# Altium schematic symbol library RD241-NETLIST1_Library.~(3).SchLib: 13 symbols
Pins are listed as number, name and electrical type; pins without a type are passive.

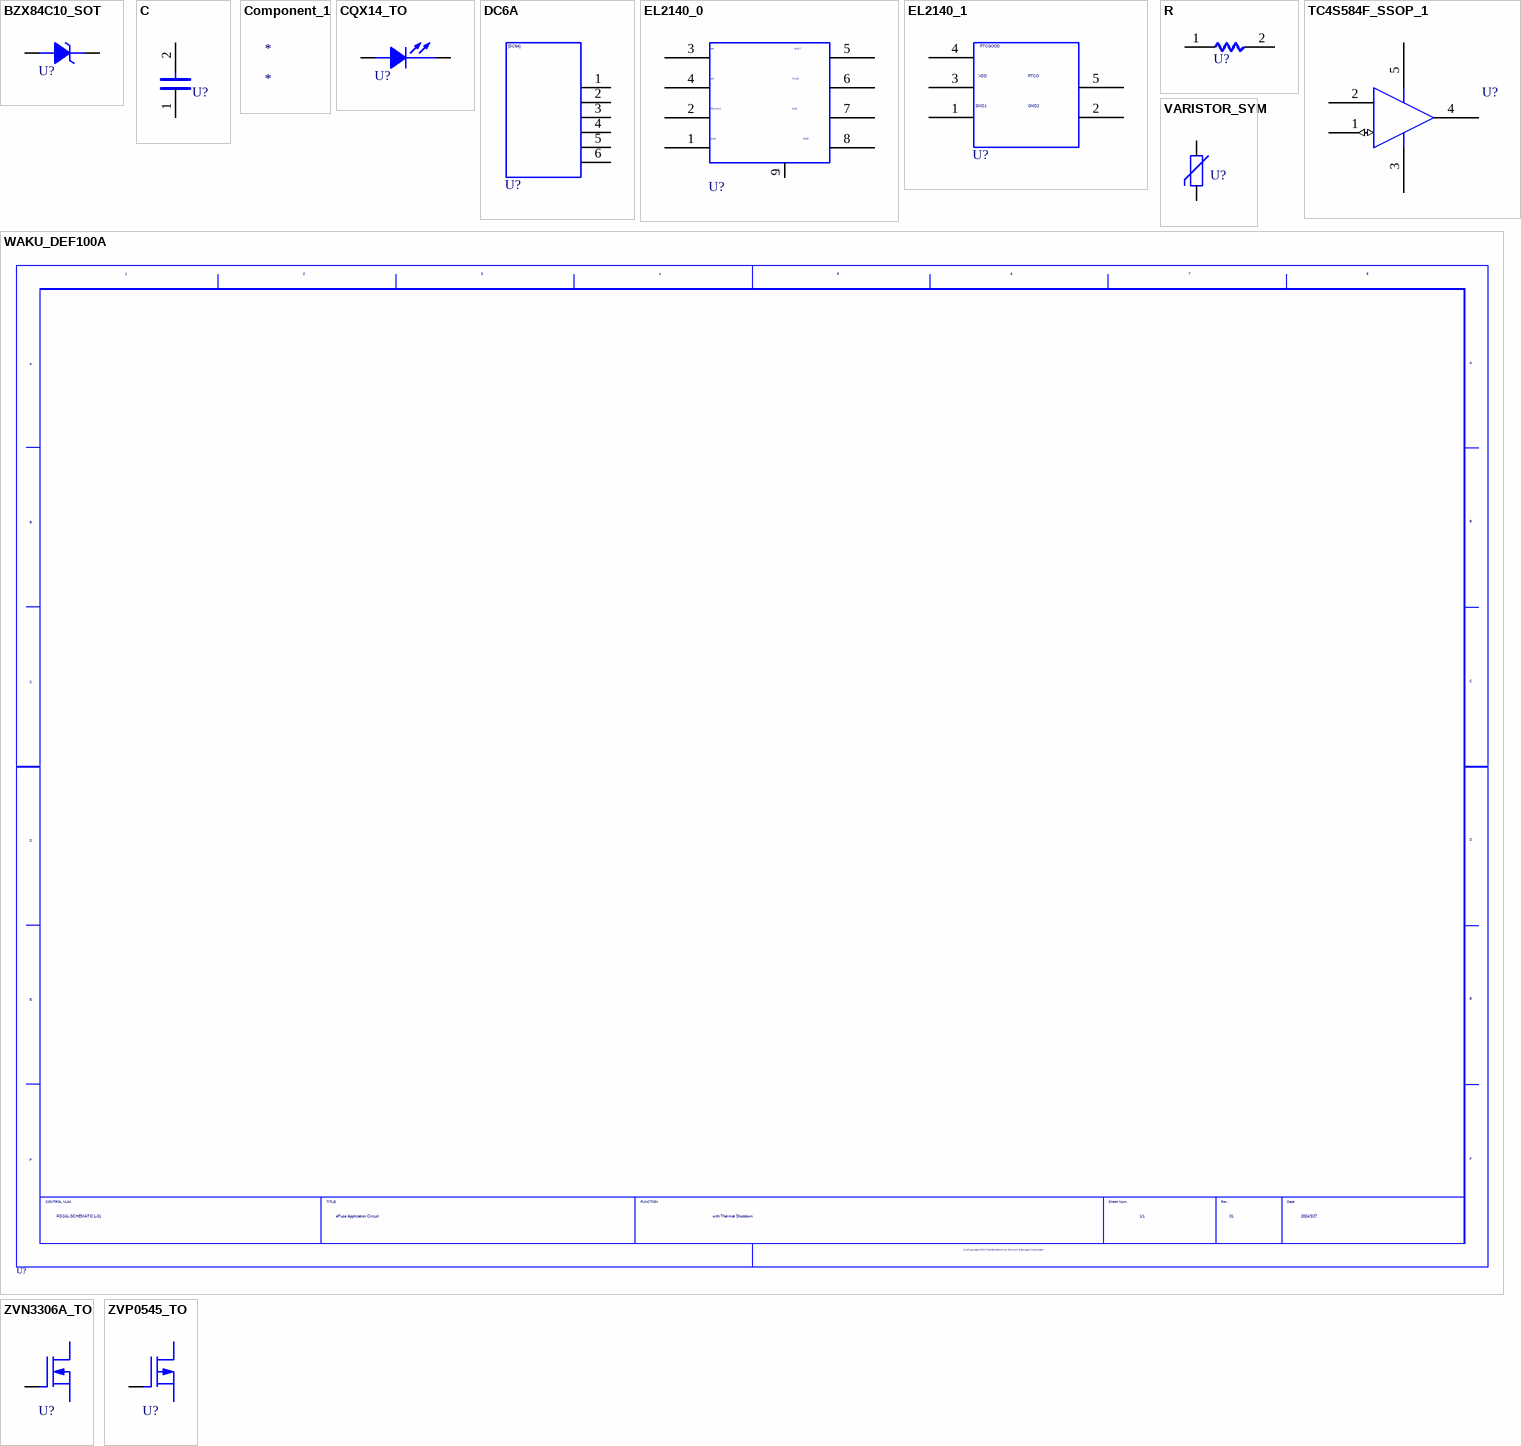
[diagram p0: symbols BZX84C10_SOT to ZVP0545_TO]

## BZX84C10_SOT
designator U?  (value not drawn)
TIME: 12:45:09; UPDATEUSER: t5459927; SAVECOUNT: 2; __TIME_0__: 1711511109; __FILE_0__: C:/Users/t5459927/Desktop/RD228/RD241_242/DISCRETE/BZX84C10_SOT.smb; __HOST_0__: t5459927-02; __$Database_ID__: Z-4d996314-a8f2-4553-8b05-67113f3b3349; OriginalSymbolOrigin: (0,0); Altium-Right: 30; Altium-Bottom: 20
pins: 1 ANODE, 3 CATHODE

## C
designator U?  (value not drawn)
TIME: 12:45:10; UPDATEUSER: t5459927; SAVECOUNT: 2; ORIGINALSYMBOLORIGIN: (0,0); __TIME_0__: 1711511110; __FILE_0__: C:/Users/t5459927/Desktop/RD228/RD241_242/SMB006/C.smb; __HOST_0__: t5459927-02; __$Database_ID__: Z-2ed5c0e2-f3bf-4eaa-903b-98ed9c52cb7a; Altium-Right: 20; Altium-Bottom: 10
pins: 1, 2

## Component_1
designator *

## CQX14_TO
designator U?  (value not drawn)
TIME: 12:45:09; UPDATEUSER: t5459927; SAVECOUNT: 2; __TIME_0__: 1711511109; __FILE_0__: C:/Users/t5459927/Desktop/RD228/RD241_242/DISCRETE/CQX14_TO.smb; __HOST_0__: t5459927-02; __$Database_ID__: Z-1cb6e29b-ad43-4461-94ab-d8e4d2707aaf; OriginalSymbolOrigin: (0,0); Altium-Right: 40; Altium-Bottom: 20
pins: 1 CATHODE, 3 ANODE

## DC6A
designator U?  (value not drawn)
TIME: 13:28:28; UPDATEUSER: e1023210; UPDATETIME: 18:37:18; SAVECOUNT: 24; SAVEAREA0: -19103,0,39483,27940; ORIGINALSYMBOLORIGIN: (0,0); Altium-Right: 50; Altium-Bottom: 90
pins: 1, 2, 3, 4, 5, 6

## EL2140_0
designator U?  (value not drawn)
TIME: 12:45:12; UPDATEUSER: t5459927; UPDATETIME: 14:48:14; SAVECOUNT: 4; OriginalSymbolOrigin: (7620,0); Altium-Right: 80
pins: 1, 2, 3, 4, 5, 6, 7, 8, 9

## EL2140_1
designator U?  (value not drawn)
TIME: 12:45:11; UPDATEUSER: t5459927; UPDATETIME: 14:01:54; SAVECOUNT: 3; OriginalSymbolOrigin: (0,0); Altium-Right: 70
pins: 1, 2, 3, 4, 5

## R
designator U?  (value not drawn)
TIME: 12:45:10; UPDATEUSER: t5459927; SAVECOUNT: 2; ORIGINALSYMBOLORIGIN: (0,0); __TIME_0__: 1711511110; __FILE_0__: C:/Users/t5459927/Desktop/RD228/RD241_242/WORK_EDIF_SERVER1_6KW_SD_SMB007/R.smb; __HOST_0__: t5459927-02; __$Database_ID__: Z-26c83a47-3c15-4f79-b1a7-540f9e8407cf; Altium-Right: 20
pins: 1, 2

## TC4S584F_SSOP_1
designator U?  (value not drawn)
TIME: 12:45:11; UPDATEUSER: t5459927; UPDATETIME: 14:51:38; SAVECOUNT: 3; OriginalSymbolOrigin: (0,0); Altium-Right: 40
pins: 1 (io), 2, 3, 4, 5

## VARISTOR_SYM
designator U?  (value not drawn)
TIME: 12:45:09; UPDATEUSER: t5459927; SAVECOUNT: 2; __TIME_0__: 1711511109; __FILE_0__: C:/Users/t5459927/Desktop/RD228/RD241_242/DISCRETE/VARISTOR_SYM.smb; __HOST_0__: t5459927-02; __$Database_ID__: Z-408d415e-1fb1-46aa-bdfc-9f261eeb8e75; OriginalSymbolOrigin: (0,0); Altium-Right: 20
pins: 1, 2

## WAKU_DEF100A
designator U?, comment DATE: 2024/3/27  REVISION: 01  SHEETNUMBER: 1/1  TITLE: eFuse Application Circuit  FUNCTION: with Thermal Shutdown  DRAWINGNUMBER: RD241-SCHEMATIC1-01  (hidden comment: WAKU_DEF100)
TIME: 14:30:25; UPDATEUSER: cae; UPDATETIME: 18:29:18; SAVECOUNT: 3; PLOTTIME: HH:MM; SAVEAREA0: -97960,-271444,497068,-316; ORIGINALSYMBOLORIGIN: (0,0); __TIME_0__: 1711511106; __USER_0__: t5459927; __FILE_0__: C:/Users/t5459927/Desktop/RD228/RD241_242/SMB008/WAKU_DEF100.smb; __HOST_0__: t5459927-02; __$Database_ID__: Z-c202f42d-4400-46ba-87ce-01e3b7045849; Altium-Right: 1570; Altium-Bottom: 1070

## ZVN3306A_TO
designator U?  (value not drawn)
TIME: 12:45:10; UPDATEUSER: t5459927; SAVECOUNT: 2; __TIME_0__: 1711511110; __FILE_0__: C:/Users/t5459927/Desktop/RD228/RD241_242/TRANSISTOR/ZVN3306A_TO.smb; __HOST_0__: t5459927-02; __$Database_ID__: Z-67d2e6f0-db45-4aeb-8b2f-a8031d5274fb; OriginalSymbolOrigin: (0,5080); Altium-Right: 20; Altium-Bottom: 60
pins: 1 D, 2 G, 3 S

## ZVP0545_TO
designator U?  (value not drawn)
TIME: 12:45:10; UPDATEUSER: t5459927; SAVECOUNT: 2; __TIME_0__: 1711511110; __FILE_0__: C:/Users/t5459927/Desktop/RD228/RD241_242/TRANSISTOR/ZVP0545_TO.smb; __HOST_0__: t5459927-02; __$Database_ID__: Z-0ccab0bb-bbd5-4164-9450-f350f899c1c7; OriginalSymbolOrigin: (0,5080); Altium-Right: 20; Altium-Bottom: 60
pins: 1 D, 2 G, 3 S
